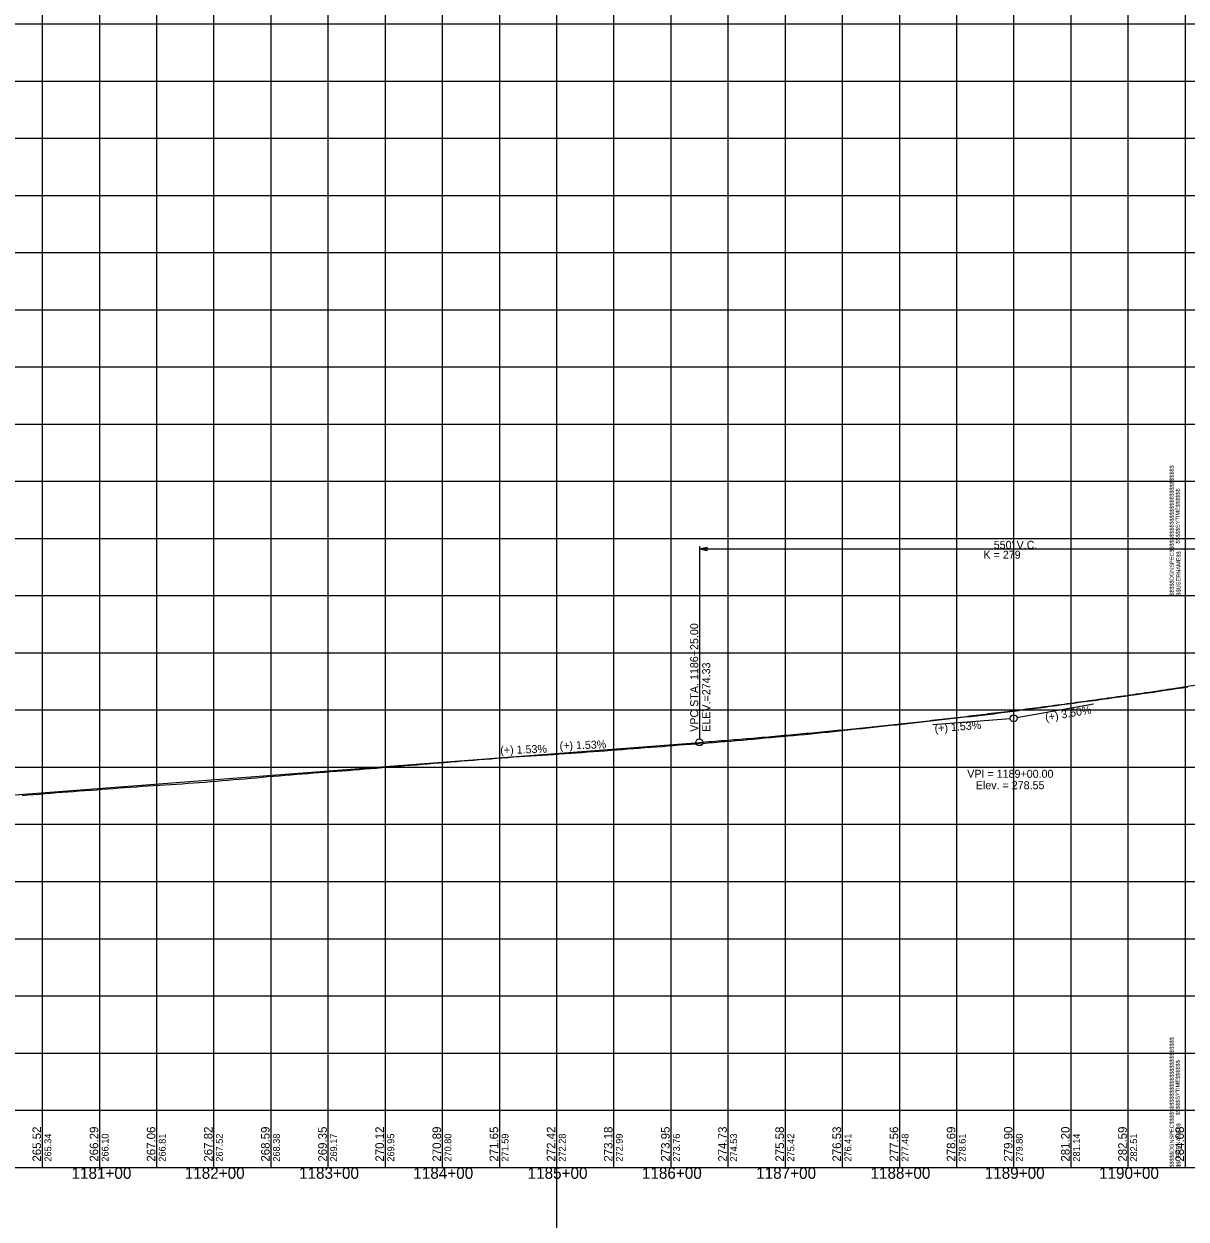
# Model space of a CAD drawing. Extents: x -90830 to 2015517, y -20856 to 836331.
# Drawn here: x 6957 to 7974, y -19432 to -18387 of the extents above; entities that cross this region are included whole.
import ezdxf

# ---------------------------------------------------------------- set-up
doc = ezdxf.new("R2010")
doc.units = 0
for name, color, linetype in [('Level 1', 7, 'Continuous'), ('RD_DDB_GradeTX', 7, 'Continuous'), ('RD_DDB_Profile_Elev', 7, 'Continuous'), ('RD_DDB_Profile_EX', 7, 'Continuous'), ('RD_DDB_Profile_Lbl', 7, 'Continuous'), ('RD_DDB_Profile_PR', 7, 'Continuous'), ('RD_DDB_StaTX', 7, 'Continuous'), ('RD_DDB_StripGrade', 7, 'Continuous'), ('RD_DDB_VCLbl', 7, 'Continuous'), ('RD_GPK_Profile_Cell', 7, 'Continuous'), ('RD_TX_Drainage', 7, 'Continuous')]:
    doc.layers.add(name, color=color, linetype=linetype)

msp = doc.modelspace()

# ---------------------------------------------------------------- linework, layer by layer
at = {"layer": 'Level 1'}
for p, q in [((7423.5, -12693.4), (7423.5, -20856.1)), ((6973.5, -17886.5), (6973.5, -18386.5)), ((7023.5, -17886.5), (7023.5, -18386.5)), ((7073.5, -17886.5), (7073.5, -18386.5)), ((7123.5, -17886.5), (7123.5, -18386.5)), ((7173.5, -17886.5), (7173.5, -18386.5)), ((7223.5, -17886.5), (7223.5, -18386.5)), ((7273.5, -17886.5), (7273.5, -18386.5)), ((7323.5, -17886.5), (7323.5, -18386.5)), ((7373.5, -17886.5), (7373.5, -18386.5)), ((7423.5, -17886.5), (7423.5, -18386.5)), ((7473.5, -17886.5), (7473.5, -18386.5)), ((7523.5, -17886.5), (7523.5, -18386.5)), ((7573.5, -17886.5), (7573.5, -18386.5)), ((7623.5, -17886.5), (7623.5, -18386.5)), ((7673.5, -17886.5), (7673.5, -18386.5)), ((7723.5, -17886.5), (7723.5, -18386.5)), ((7773.5, -17886.5), (7773.5, -18386.5)), ((7823.5, -17886.5), (7823.5, -18386.5)), ((7873.5, -17886.5), (7873.5, -18386.5)), ((7923.5, -17886.5), (7923.5, -18386.5)), ((7973.5, -17886.5), (7973.5, -18386.5)), ((7973.5, -17886.5), (7973.5, -18386.5)), ((7973.5, -17886.5), (7973.5, -18386.5)), ((6373.5, -18386.5), (7973.5, -18386.5)), ((6373.5, -18386.5), (7973.5, -18386.5)), ((6973.5, -18386.5), (6973.5, -18886.5)), ((7023.5, -18386.5), (7023.5, -18886.5)), ((7073.5, -18386.5), (7073.5, -18886.5)), ((7123.5, -18386.5), (7123.5, -18886.5)), ((7173.5, -18386.5), (7173.5, -18886.5)), ((7223.5, -18386.5), (7223.5, -18886.5)), ((7273.5, -18386.5), (7273.5, -18886.5)), ((7323.5, -18386.5), (7323.5, -18886.5)), ((7373.5, -18386.5), (7373.5, -18886.5)), ((7423.5, -18386.5), (7423.5, -18886.5)), ((7473.5, -18386.5), (7473.5, -18886.5)), ((7523.5, -18386.5), (7523.5, -18886.5)), ((7573.5, -18386.5), (7573.5, -18886.5)), ((7623.5, -18386.5), (7623.5, -18886.5)), ((7673.5, -18386.5), (7673.5, -18886.5)), ((7723.5, -18386.5), (7723.5, -18886.5)), ((7773.5, -18386.5), (7773.5, -18886.5)), ((7823.5, -18386.5), (7823.5, -18886.5)), ((7873.5, -18386.5), (7873.5, -18886.5)), ((7923.5, -18386.5), (7923.5, -18886.5)), ((7973.5, -18386.5), (7973.5, -18886.5)), ((7973.5, -18386.5), (7973.5, -18886.5)), ((7973.5, -18386.5), (9573.5, -18386.5)), ((7973.5, -18386.5), (7973.5, -18886.5)), ((7973.5, -18386.5), (9573.5, -18386.5)), ((6373.5, -18436.5), (7973.5, -18436.5)), ((7973.5, -18436.5), (9573.5, -18436.5)), ((6373.5, -18486.5), (7973.5, -18486.5)), ((7973.5, -18486.5), (9573.5, -18486.5)), ((6373.5, -18536.5), (7973.5, -18536.5)), ((7973.5, -18536.5), (9573.5, -18536.5)), ((6373.5, -18586.5), (7973.5, -18586.5)), ((7973.5, -18586.5), (9573.5, -18586.5)), ((6373.5, -18636.5), (7973.5, -18636.5)), ((7973.5, -18636.5), (9573.5, -18636.5)), ((6373.5, -18686.5), (7973.5, -18686.5)), ((7973.5, -18686.5), (9573.5, -18686.5)), ((6373.5, -18736.5), (7973.5, -18736.5)), ((7973.5, -18736.5), (9573.5, -18736.5)), ((6373.5, -18786.5), (7973.5, -18786.5)), ((7973.5, -18786.5), (9573.5, -18786.5)), ((6373.5, -18836.5), (7973.5, -18836.5)), ((7973.5, -18836.5), (9573.5, -18836.5)), ((6373.5, -18886.5), (7973.5, -18886.5)), ((6373.5, -18886.5), (7973.5, -18886.5)), ((6973.5, -18886.5), (6973.5, -19386.5)), ((7023.5, -18886.5), (7023.5, -19386.5)), ((7073.5, -18886.5), (7073.5, -19386.5)), ((7123.5, -18886.5), (7123.5, -19386.5)), ((7173.5, -18886.5), (7173.5, -19386.5)), ((7223.5, -18886.5), (7223.5, -19386.5)), ((7273.5, -18886.5), (7273.5, -19386.5)), ((7323.5, -18886.5), (7323.5, -19386.5)), ((7373.5, -18886.5), (7373.5, -19386.5)), ((7423.5, -18886.5), (7423.5, -19386.5)), ((7473.5, -18886.5), (7473.5, -19386.5)), ((7523.5, -18886.5), (7523.5, -19386.5)), ((7573.5, -18886.5), (7573.5, -19386.5)), ((7623.5, -18886.5), (7623.5, -19386.5)), ((7673.5, -18886.5), (7673.5, -19386.5)), ((7723.5, -18886.5), (7723.5, -19386.5)), ((7773.5, -18886.5), (7773.5, -19386.5)), ((7823.5, -18886.5), (7823.5, -19386.5)), ((7873.5, -18886.5), (7873.5, -19386.5)), ((7923.5, -18886.5), (7923.5, -19386.5)), ((7973.5, -18886.5), (7973.5, -19386.5)), ((7973.5, -18886.5), (7973.5, -19386.5)), ((7973.5, -18886.5), (9573.5, -18886.5)), ((7973.5, -18886.5), (9573.5, -18886.5)), ((7973.5, -18886.5), (7973.5, -19386.5)), ((6373.5, -18936.5), (7973.5, -18936.5)), ((7973.5, -18936.5), (9573.5, -18936.5)), ((6373.5, -18986.5), (7973.5, -18986.5)), ((7973.5, -18986.5), (9573.5, -18986.5)), ((6373.5, -19036.5), (7973.5, -19036.5)), ((7973.5, -19036.5), (9573.5, -19036.5)), ((6373.5, -19086.5), (7973.5, -19086.5)), ((7973.5, -19086.5), (9573.5, -19086.5)), ((6373.5, -19136.5), (7973.5, -19136.5)), ((7973.5, -19136.5), (9573.5, -19136.5)), ((6373.5, -19186.5), (7973.5, -19186.5)), ((7973.5, -19186.5), (9573.5, -19186.5)), ((6373.5, -19236.5), (7973.5, -19236.5)), ((7973.5, -19236.5), (9573.5, -19236.5)), ((6373.5, -19286.5), (7973.5, -19286.5)), ((7973.5, -19286.5), (9573.5, -19286.5)), ((6373.5, -19336.5), (7973.5, -19336.5)), ((7973.5, -19336.5), (9573.5, -19336.5)), ((6373.5, -19386.5), (7973.5, -19386.5)), ((7973.5, -19386.5), (9573.5, -19386.5))]:
    msp.add_line(p, q, dxfattribs=at)
at = {"layer": 'RD_DDB_GradeTX'}
for p, q in [((7893.4, -18981.5), (7826.4, -18993.3)), ((7752.7, -18999.2), (7820.5, -18994))]:
    msp.add_line(p, q, dxfattribs=at)
msp.add_circle((7823.5, -18993.8), 3, dxfattribs=at)
at = {"layer": 'RD_DDB_Profile_EX'}
for points in [[(7545.9, -19016), (7550.9, -19015.7), (7555.9, -19015.3), (7560.9, -19014.9), (7565.9, -19014.5), (7570.9, -19014.1), (7575.9, -19013.7), (7580.9, -19013.2), (7585.9, -19012.8), (7590.9, -19012.3), (7595.9, -19011.9), (7600.9, -19011.4), (7605.9, -19011), (7610.9, -19010.5), (7615.9, -19010.1), (7620.9, -19009.6), (7625.9, -19009.2), (7630.9, -19008.7), (7635.9, -19008.3), (7640.9, -19007.8), (7645.9, -19007.3), (7650.9, -19006.8), (7655.9, -19006.3), (7660.9, -19005.8), (7665.9, -19005.3), (7670.9, -19004.7), (7675.9, -19004.2), (7680.9, -19003.7), (7685.9, -19003.1), (7690.9, -19002.6), (7695.9, -19002), (7700.9, -19001.5), (7705.9, -19001), (7710.9, -19000.4), (7715.9, -18999.9), (7720.9, -18999.4), (7725.9, -18998.8), (7730.9, -18998.3), (7735.9, -18997.7), (7740.9, -18997.2), (7745.9, -18996.6), (7750.9, -18996), (7755.9, -18995.4), (7760.9, -18994.9), (7765.9, -18994.3), (7770.9, -18993.8), (7775.9, -18993.2), (7780.9, -18992.6), (7785.9, -18992.1), (7790.9, -18991.5), (7795.9, -18991), (7800.9, -18990.4), (7805.9, -18989.8), (7810.9, -18989.1), (7815.9, -18988.5), (7820.9, -18987.9), (7825.9, -18987.2), (7830.9, -18986.5), (7835.9, -18985.9), (7840.9, -18985.2), (7845.9, -18984.5), (7850.9, -18983.9), (7855.9, -18983.2), (7860.9, -18982.5), (7865.9, -18981.8), (7870.9, -18981.2), (7875.9, -18980.5), (7880.9, -18979.8), (7885.9, -18979.1), (7890.9, -18978.4), (7895.9, -18977.8), (7900.9, -18977.1), (7905.9, -18976.4), (7910.9, -18975.7), (7915.9, -18975), (7920.9, -18974.3), (7925.9, -18973.6), (7930.9, -18972.9), (7935.9, -18972.2), (7940.9, -18971.5), (7945.9, -18970.8), (7950.9, -18970), (7955.9, -18969.3), (7960.9, -18968.5), (7965.9, -18967.8), (7970.9, -18967), (7975.9, -18966.3)], [(7045.9, -19054.3), (7050.9, -19053.9), (7055.9, -19053.6), (7060.9, -19053.2), (7065.9, -19052.9), (7070.9, -19052.6), (7075.9, -19052.3), (7080.9, -19052), (7085.9, -19051.6), (7090.9, -19051.3), (7095.9, -19051), (7100.9, -19050.6), (7105.9, -19050.3), (7110.9, -19049.9), (7115.9, -19049.5), (7120.9, -19049.1), (7125.9, -19048.7), (7130.9, -19048.3), (7135.9, -19047.9), (7140.9, -19047.4), (7145.9, -19047), (7150.9, -19046.6), (7155.9, -19046.2), (7160.9, -19045.7), (7165.9, -19045.3), (7170.9, -19044.8), (7175.9, -19044.4), (7180.9, -19044), (7185.9, -19043.6), (7190.9, -19043.2), (7195.9, -19042.7), (7200.9, -19042.3), (7205.9, -19042), (7210.9, -19041.6), (7215.9, -19041.2), (7220.9, -19040.8), (7225.9, -19040.4), (7230.9, -19040.1), (7235.9, -19039.7), (7240.9, -19039.3), (7245.9, -19038.9), (7250.9, -19038.5), (7255.9, -19038.1), (7260.9, -19037.7), (7265.9, -19037.3), (7270.9, -19036.9), (7275.9, -19036.5), (7280.9, -19036.1), (7285.9, -19035.7), (7290.9, -19035.2), (7295.9, -19034.8), (7300.9, -19034.4), (7305.9, -19034), (7310.9, -19033.6), (7315.9, -19033.1), (7320.9, -19032.7), (7325.9, -19032.3), (7330.9, -19031.9), (7335.9, -19031.5), (7340.9, -19031.1), (7345.9, -19030.7), (7350.9, -19030.3), (7355.9, -19029.9), (7360.9, -19029.5), (7365.9, -19029.1), (7370.9, -19028.7), (7375.9, -19028.3), (7380.9, -19028), (7385.9, -19027.6), (7390.9, -19027.3), (7395.9, -19027), (7400.9, -19026.6), (7405.9, -19026.3), (7410.9, -19025.9), (7415.9, -19025.6), (7420.9, -19025.3), (7425.9, -19024.9), (7430.9, -19024.6), (7435.9, -19024.3), (7440.9, -19023.9), (7445.9, -19023.6), (7450.9, -19023.2), (7455.9, -19022.8), (7460.9, -19022.5), (7465.9, -19022.1), (7470.9, -19021.7), (7475.9, -19021.3), (7480.9, -19021), (7485.9, -19020.6), (7490.9, -19020.2), (7495.9, -19019.8), (7500.9, -19019.4), (7505.9, -19019), (7510.9, -19018.7), (7515.9, -19018.3), (7520.9, -19017.9), (7525.9, -19017.5), (7530.9, -19017.1), (7535.9, -19016.8), (7540.9, -19016.4), (7545.9, -19016)], [(6955.9, -19061.2), (6960.9, -19060.8), (6965.9, -19060.4), (6970.9, -19060), (6975.9, -19059.6), (6980.9, -19059.2), (6985.9, -19058.8), (6990.9, -19058.5), (6995.9, -19058.1), (7000.9, -19057.7), (7005.9, -19057.3), (7010.9, -19057), (7015.9, -19056.6), (7020.9, -19056.2), (7025.9, -19055.8), (7030.9, -19055.4), (7035.9, -19055.1), (7040.9, -19054.7), (7045.9, -19054.3)]]:
    msp.add_lwpolyline(points, dxfattribs=at)
at = {"layer": 'RD_DDB_Profile_PR'}
msp.add_line((6923.5, -19062.7), (7548.5, -19014.8), dxfattribs=at)
msp.add_spline([(7548.5, -19014.8), (7559.5, -19014), (7570.5, -19013.1), (7581.5, -19012.2), (7592.5, -19011.3), (7603.5, -19010.4), (7614.5, -19009.4), (7625.5, -19008.4), (7636.5, -19007.4), (7647.5, -19006.4), (7658.5, -19005.3), (7669.5, -19004.3), (7680.5, -19003.2), (7691.5, -19002.1), (7702.5, -19000.9), (7713.5, -18999.8), (7724.5, -18998.6), (7735.5, -18997.4), (7746.5, -18996.2), (7757.5, -18994.9), (7768.5, -18993.7), (7779.5, -18992.4), (7790.5, -18991.1), (7801.5, -18989.7), (7812.5, -18988.4), (7823.5, -18987), (7834.5, -18985.6), (7845.5, -18984.2), (7856.5, -18982.8), (7867.5, -18981.3), (7878.5, -18979.8), (7889.5, -18978.3), (7900.5, -18976.8), (7911.5, -18975.2), (7922.5, -18973.7), (7933.5, -18972.1), (7944.5, -18970.5), (7955.5, -18968.8), (7966.5, -18967.2), (7977.5, -18965.5), (7988.5, -18963.8), (7999.5, -18962.1), (8010.5, -18960.4), (8021.5, -18958.6), (8032.5, -18956.8), (8043.5, -18955), (8054.5, -18953.2), (8065.5, -18951.3), (8076.5, -18949.5), (8087.5, -18947.6), (8098.5, -18945.6)], degree=3, dxfattribs=at)
at = {"layer": 'RD_DDB_VCLbl'}
for p, q in [((7548.5, -18843.1), (7548.5, -19011.8)), ((7548.5, -18845.6), (8098.5, -18845.6))]:
    msp.add_line(p, q, dxfattribs=at)
msp.add_circle((7548.5, -19014.8), 3, dxfattribs=at)
at = {"layer": 'RD_GPK_Profile_Cell'}
msp.add_line((4823.5, -19386.5), (75223.5, -19386.5), dxfattribs=at)
at = {"layer": 'RD_TX_Drainage'}
msp.add_lwpolyline([(7555.1, -18847.3), (7548.5, -18845.6), (7555.1, -18844)], close=True, dxfattribs=at)

# ---------------------------------------------------------------- texts
at = {"layer": 'Level 1'}
for s, p in [('$$$$$DGNSPEC$$$$$$$$$$$$$$$$$$$$$$$$$$$$', (7963.6, -18886.6)), ('$$$$$SYTIME$$$$$$', (7968.9, -18841)), ('$$USERNAME$$', (7969.5, -18886.4)), ('$$$$$DGNSPEC$$$$$$$$$$$$$$$$$$$$$$$$$$$$', (7963.6, -19386.6)), ('$$$$$SYTIME$$$$$$', (7968.9, -19341)), ('$$USERNAME$$', (7969.5, -19386.4))]:
    msp.add_text(s, height=3.544, rotation=90, dxfattribs=at).set_placement(p)
at = {"layer": 'RD_DDB_GradeTX'}
for s, rotation, p in [('(+) 3.50%', 9.9263, (7851.7, -18996.5)), ('(+) 1.53%', 4.3803, (7754.6, -19006.1)), ('(+) 1.53%', 1.6333, (7374.4, -19025.1)), ('(+) 1.53%', 1.6333, (7426.3, -19021.2))]:
    msp.add_text(s, height=7, rotation=rotation, dxfattribs=at).set_placement(p)
at = {"layer": 'RD_DDB_Profile_Elev'}
for s, p in [('265.52', (6972.5, -19381.5)), ('266.29', (7022.5, -19381.5)), ('267.06', (7072.5, -19381.5)), ('267.82', (7122.5, -19381.5)), ('268.59', (7172.5, -19381.5)), ('269.35', (7222.5, -19381.5)), ('270.12', (7272.5, -19381.5)), ('270.89', (7322.5, -19381.5)), ('271.65', (7372.5, -19381.5)), ('272.42', (7422.5, -19381.5)), ('273.18', (7472.5, -19381.5)), ('273.95', (7522.5, -19381.5)), ('274.73', (7572.5, -19381.5)), ('275.58', (7622.5, -19381.5)), ('276.53', (7672.5, -19381.5)), ('277.56', (7722.5, -19381.5)), ('278.69', (7772.5, -19381.5)), ('279.90', (7822.5, -19381.5)), ('281.20', (7872.5, -19381.5)), ('282.59', (7922.5, -19381.5)), ('284.08', (7972.5, -19381.5))]:
    msp.add_text(s, height=7.5, rotation=90, dxfattribs=at).set_placement(p)
at = {"layer": 'RD_DDB_Profile_Lbl'}
for s, p in [('VPI = 1189+00.00', (7782.9, -19045.8)), ('Elev. = 278.55', (7790.4, -19055.8))]:
    msp.add_text(s, height=7, dxfattribs=at).set_placement(p)
at = {"layer": 'RD_DDB_StaTX'}
for s, p in [('1181+00', (6999.1, -19396.5)), ('1182+00', (7098.2, -19396.5)), ('1183+00', (7198.2, -19396.5)), ('1184+00', (7298.2, -19396.5)), ('1185+00', (7398.2, -19396.5)), ('1186+00', (7498.2, -19396.5)), ('1187+00', (7598.2, -19396.5)), ('1188+00', (7698.2, -19396.5)), ('1189+00', (7798.2, -19396.5)), ('1190+00', (7898.2, -19396.5))]:
    msp.add_text(s, height=10, dxfattribs=at).set_placement(p)
at = {"layer": 'RD_DDB_StripGrade'}
for s, height, p in [('VPC STA. 1186+25.00 ', 7, (7547.5, -19005.6)), ('ELEV.=274.33', 7, (7558, -19005.6)), ('265.34', 6, (6981.5, -19381.5)), ('266.10', 6, (7031.5, -19381.5)), ('266.81', 6, (7081.5, -19381.5)), ('267.52', 6, (7131.5, -19381.5)), ('268.38', 6, (7181.5, -19381.5)), ('269.17', 6, (7231.5, -19381.5)), ('269.95', 6, (7281.5, -19381.5)), ('270.80', 6, (7331.5, -19381.5)), ('271.59', 6, (7381.5, -19381.5)), ('272.28', 6, (7431.5, -19381.5)), ('272.99', 6, (7481.5, -19381.5)), ('273.76', 6, (7531.5, -19381.5)), ('274.53', 6, (7581.5, -19381.5)), ('275.42', 6, (7631.5, -19381.5)), ('276.41', 6, (7681.5, -19381.5)), ('277.48', 6, (7731.5, -19381.5)), ('278.61', 6, (7781.5, -19381.5)), ('279.80', 6, (7831.5, -19381.5)), ('281.14', 6, (7881.5, -19381.5)), ('282.51', 6, (7931.5, -19381.5))]:
    msp.add_text(s, height=height, rotation=90, dxfattribs=at).set_placement(p)
at = {"layer": 'RD_DDB_VCLbl'}
for s, p in [("550' V.C.", (7806.1, -18845.6)), ('K = 279', (7797.1, -18854.2))]:
    msp.add_text(s, height=7, dxfattribs=at).set_placement(p)

doc.saveas('drawing.dxf')
